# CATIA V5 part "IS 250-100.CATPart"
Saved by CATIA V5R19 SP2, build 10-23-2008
Part number: IS 250-100
Bounding box of the stored display mesh (mm): x -18.951 to 18.951, y -18.952 to 18.952, z 0 to 250
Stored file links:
  C:\Users\Bora\Desktop\3D Katı model\IS serisi\IS 250\IS 250-100.CATPart
  C:\Program Files\Dassault Systemes\B19\intel_a\reffiles\standard\MetricThickPitch.txt
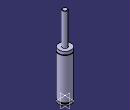
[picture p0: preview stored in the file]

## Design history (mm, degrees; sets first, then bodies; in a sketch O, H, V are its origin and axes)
Body1 (main body)
  Sketch1 on yz-plane, origin (0, 0, 0), H (0, 1, 0), V (0, 0, 1)
    point P3 (7.5, 249)
    point P5 (7.5, 249)
    point P7 (19, 138.5)
    point P8 (19, 136.5)
    point P12 (19, 136.5)
    point P13 (19, 138.5)
    line L1 (19, 0) -> (19, 4)
    line L2 (7.5, 249) -> (7.5, 148)
    arc A1 centre (6.5, 249) radius 1 from (7.5, 249) to (6.5, 250) ccw
    arc A2 centre (19, 137.5) radius 1 from (19, 138.5) to (19, 136.5) ccw
    line L3 (16.5, 7.5) -> (16.5, 4)
    line L4 (19, 7.5) -> (19, 136.5)
    line L5 (19, 138.5) -> (19, 148)
    line L6 (6.5, 250) -> (0, 250)
    point P15 (0, 250)
    line L7 (7.5, 148) -> (19, 148)
    line L8 (16.5, 7.5) -> (19, 7.5)
    line L9 (16.5, 4) -> (19, 4)
    line L10 (0, 0) -> (19, 0)
    coincidence: P15 V, P3 P5, P7 P13, P8 P12
    tangency: L6 A1
    horizontal: L7 H, L8 H, L9 H, L10 H
  Shaft1: profile Sketch1, axis Sketch1.V, angle 360
  Sketch2 on face of Shaft1 from Sketch1.L10, origin (0, 0, 0), H (1, 0, 0), V (0, -1, 0)
    point P1 (0, 0)
  Hole1: placed by Sketch2, at (0, 0, 0) direction (0, 0, 1), diameter 6.647, depth 7, threaded "M8", thread diameter 8, thread depth 7, pitch 1.25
